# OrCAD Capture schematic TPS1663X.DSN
size A
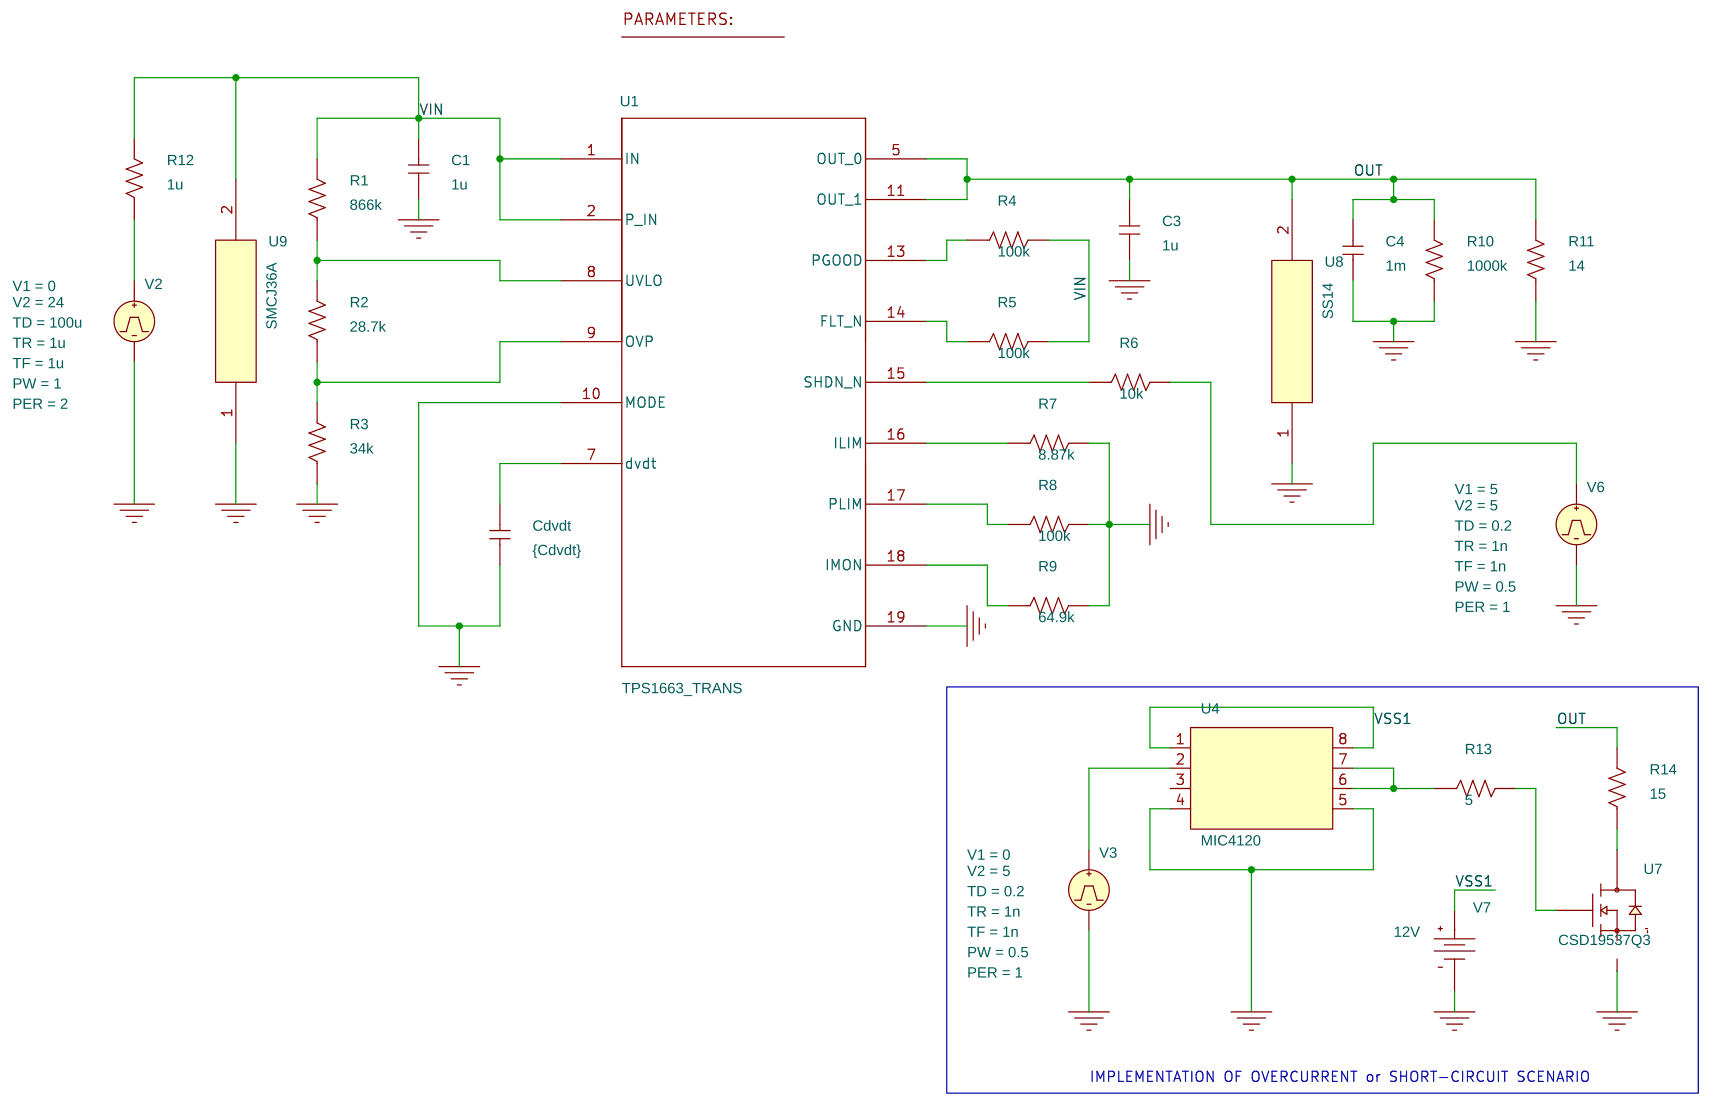
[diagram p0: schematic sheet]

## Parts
1  PARAM
C1  1u  [cap196]
C3  1u  [cap196]
C4  1m  [cap196]
Cdvdt  {Cdvdt}  [cap196]
R1  866k  [AXRC05]
R2  28.7k  [AXRC05]
R3  34k  [AXRC05]
R4  100k  [AXRC05]
R5  100k  [AXRC05]
R6  10k  [AXRC05]
R7  8.87k  [AXRC05]
R8  100k  [AXRC05]
R9  64.9k  [AXRC05]
R10  1000k  [AXRC05]
R11  14  [AXRC05]
R12  1u  [AXRC05]
R13  5  [AXRC05]
R14  15  [AXRC05]
U1  TPS1663_TRANS  [DRC0010J]
U4  MIC4120
U7  CSD19537Q3
U8  SS14
U9  SMCJ36A
V2  VPULSE
V3  VPULSE
V6  VPULSE
V7  VDC

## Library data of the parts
1 = PARAM: Adjustable_Output_Power_Limit: 0; Cdvdt: 160n; Overvoltage_Protection: 0
C1 C3 C4 Cdvdt = C
R1-R14 = R
U1 = TPS1663_TRANS
U4 = MIC4120
U7 = CSD19537Q3
U8 = SS14
U9 = SMCJ36A
V2 = VPULSE: PER: 2; PW: 1; TD: 100u; TF: 1u; TR: 1u; V1: 0; V2: 24
V3 = VPULSE: PER: 1; PW: 0.5; TD: 0.2; TF: 1n; TR: 1n; V1: 0; V2: 5
V6 = VPULSE: PER: 1; PW: 0.5; TD: 0.2; TF: 1n; TR: 1n; V1: 5; V2: 5
V7 = VDC: DC: 12V

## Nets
VIN: C1.2 R1.2 R4.2 R5.2 R12.2 U1.1(IN) U1.2(P_IN) U9.2
VSS1: U4.1(VS) U4.8(VS1) V7.0(+)
0: C1.1 C3.1 C4.1 Cdvdt.1 R3.1 R7.2 R8.2 R9.2 R10.1 R11.1 U1.10(MODE) U1.19(GND) U4.4(GND) U4.5(GND1) U7.1(source) U8.1 U9.1 V2.2(-) V3.2(-) V6.2(-) V7.1(-)
OUT: C3.2 C4.2 R10.2 R11.2 R14.2 U1.5(OUT_0) U1.11(OUT_1) U8.2
N00474: R1.1 R2.2 U1.8(UVLO)
N00478: R2.1 R3.2 U1.9(OVP)
N00490: Cdvdt.2 U1.7(dvdt)
N00694: R4.1 U1.13(PGOOD)
N00706: R5.1 U1.14(FLT_N)
N00726: R6.1 U1.15(SHDN_N)
N00810: R6.2 V6.1(+)
N00818: R8.1 U1.17(PLIM)
N00840: R7.1 U1.16(ILIM)
N00844: R9.1 U1.18(IMON)
N04419: R12.1 V2.1(+)
N05007: U4.2(IN) V3.1(+)
N05897: R13.1 U4.6(OUT) U4.7(OUT1)
N05901: R13.2 U7.2(gate)
N11812: R14.1 U7.3(drain)

Not connected (* = marked no-connect by the designer): U4 3(NC)

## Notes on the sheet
- IMPLEMENTATION OF OVERCURRENT or SHORT-CIRCUIT SCENARIO
